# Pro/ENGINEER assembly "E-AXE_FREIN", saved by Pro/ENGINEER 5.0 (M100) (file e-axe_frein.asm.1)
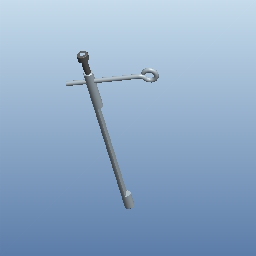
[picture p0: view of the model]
Units: millimeter Newton Second (mmNs); MM, TONNE, HOURS

Other components: 10-AXE_FREIN, 11-LEVIER, VIS_CHC_M-4X16

Other named items: A-DROITE, A-DESSUS, A-FACE, A-R0, ACS0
